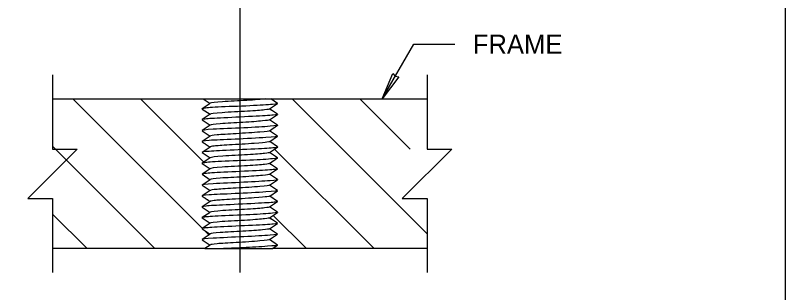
# Model space of a CAD drawing. Extents: x 99862 to 103151, y 100000 to 102076.
# Drawn here: x 102508 to 103151, y 100926 to 101158 of the extents above; entities that cross this region are included whole.
import ezdxf

# ---------------------------------------------------------------- set-up
doc = ezdxf.new("R2010")
doc.units = 0
for name, color, linetype in [('Level 1', 7, 'Continuous'), ('Level 14', 7, 'Continuous'), ('Level 15', 7, 'Continuous'), ('Level 17', 7, 'Continuous'), ('Level 2', 7, 'Continuous'), ('Level 20', 7, 'Continuous')]:
    doc.layers.add(name, color=color, linetype=linetype)

msp = doc.modelspace()

# ---------------------------------------------------------------- linework, layer by layer
at = {"layer": 'Level 1'}
for p, q in [((102665.01, 101087.88), (102670.7, 101084.06)), ((102727.12, 101084.12), (102721.51, 101087.88)), ((102670.7, 101084.06), (102664.02, 101079.63)), ((102664.18, 101079.39), (102670.73, 101075)), ((102720.39, 101079.5), (102727.12, 101083.97)), ((102727.06, 101075.02), (102720.39, 101079.5)), ((102670.73, 101075), (102664.05, 101070.59)), ((102720.45, 101070.41), (102727.12, 101074.81)), ((102664.05, 101070.37), (102670.75, 101065.88)), ((102670.75, 101065.88), (102664.05, 101061.42)), ((102720.4, 101061.28), (102727.12, 101065.79)), ((102727.12, 101065.93), (102720.45, 101070.41)), ((102664.05, 101061.21), (102670.73, 101056.73)), ((102727.12, 101056.77), (102720.4, 101061.28)), ((102670.73, 101056.73), (102664.11, 101052.33)), ((102720.5, 101052.19), (102727.12, 101056.62)), ((102670.76, 101047.7), (102664.11, 101043.24)), ((102720.45, 101043.13), (102727.12, 101047.61)), ((102727.12, 101047.75), (102720.5, 101052.19)), ((102664.11, 101043.02), (102670.7, 101038.61)), ((102727.12, 101038.66), (102720.45, 101043.13)), ((102670.7, 101038.61), (102664.02, 101034.17)), ((102664.18, 101033.93), (102670.73, 101029.54)), ((102720.39, 101034.04), (102727.12, 101038.52)), ((102727.06, 101029.57), (102720.39, 101034.04)), ((102670.73, 101029.54), (102664.05, 101025.13)), ((102720.45, 101024.95), (102727.12, 101029.35)), ((102664.05, 101024.92), (102670.75, 101020.42)), ((102670.75, 101020.42), (102664.05, 101015.97)), ((102720.4, 101015.82), (102727.12, 101020.33)), ((102727.12, 101020.48), (102720.45, 101024.95)), ((102664.05, 101015.75), (102670.73, 101011.27)), ((102727.12, 101011.32), (102720.4, 101015.82)), ((102670.73, 101011.27), (102664.11, 101006.88)), ((102720.5, 101006.73), (102727.12, 101011.17)), ((102670.76, 101002.24), (102664.11, 100997.79)), ((102720.45, 100997.68), (102727.12, 101002.15)), ((102727.12, 101002.3), (102720.5, 101006.73)), ((102664.11, 100997.57), (102670.7, 100993.16)), ((102727.12, 100993.21), (102720.45, 100997.68)), ((102670.7, 100993.16), (102664.02, 100988.72)), ((102664.18, 100988.48), (102670.73, 100984.09)), ((102720.39, 100988.59), (102727.12, 100993.06)), ((102727.06, 100984.12), (102720.39, 100988.59)), ((102670.73, 100984.09), (102664.05, 100979.68)), ((102720.45, 100979.5), (102727.12, 100983.9)), ((102664.05, 100979.46), (102670.75, 100974.97)), ((102727.12, 100975.02), (102720.45, 100979.5)), ((102670.75, 100974.97), (102664.05, 100970.52)), ((102664.05, 100970.3), (102670.73, 100965.82)), ((102720.4, 100970.37), (102727.12, 100974.88)), ((102727.12, 100965.86), (102720.4, 100970.37)), ((102670.73, 100965.82), (102666.3, 100962.88)), ((102722.89, 100962.88), (102727.12, 100965.72))]:
    msp.add_line(p, q, dxfattribs=at)
msp.add_lwpolyline([(99862, 99999.5), (103151, 99999.5), (103151, 102075.5), (99862, 102075.5)], close=True, dxfattribs=at)
for points in [[(102664.11, 101052.12), (102665.82, 101050.95), (102666.46, 101050.59)], [(102666.71, 101050.37), (102670.76, 101047.7)], [(102664.11, 101006.66), (102665.82, 101005.5), (102666.46, 101005.13)], [(102666.71, 101004.92), (102670.76, 101002.24)]]:
    msp.add_lwpolyline(points, dxfattribs=at)
at = {"layer": 'Level 14'}
for p, q in [((102665.01, 101087.88), (102721.51, 101087.88)), ((102666.3, 100962.88), (102722.89, 100962.88))]:
    msp.add_line(p, q, dxfattribs=at)
for points in [[(102720.48, 101079.44), (102722, 101078.44)], [(102720.48, 101033.99), (102722, 101032.99)], [(102720.48, 100988.53), (102722, 100987.53)]]:
    msp.add_lwpolyline(points, dxfattribs=at)
for points in [[(102717.1, 101087.88), (102713.94, 101087.48), (102702.24, 101086.52), (102679.3, 101085.57), (102671.52, 101084.55), (102670.88, 101084.19)], [(102727.12, 101084.12), (102727.37, 101083.97), (102725.47, 101083.39), (102705.99, 101082.01), (102673.67, 101080.99), (102663.55, 101079.9), (102663.93, 101079.39), (102663.99, 101079.39)], [(102720.22, 101079.39), (102720.1, 101079.32), (102718.01, 101078.73), (102703.78, 101077.5), (102678.47, 101076.41), (102670.76, 101075.39), (102670.76, 101074.95)], [(102727.12, 101075.02), (102727.37, 101074.88), (102726.04, 101074.3), (102708.65, 101073.28), (102675.88, 101071.75), (102663.86, 101070.95), (102663.93, 101070.44), (102664.05, 101070.37)], [(102727.12, 101065.93), (102727.5, 101065.72), (102723.89, 101065.06), (102699.79, 101063.61), (102670.12, 101062.52), (102663.42, 101061.64), (102664.05, 101061.21)], [(102720.22, 101070.3), (102719.91, 101070.08), (102716.56, 101069.5), (102698.91, 101068.19), (102677.02, 101067.17), (102671.45, 101066.37), (102670.95, 101066.01)], [(102720.35, 101061.28), (102720.41, 101060.92), (102714.72, 101060.26), (102691.57, 101058.66), (102674.49, 101057.86), (102671.33, 101057.13), (102671.01, 101056.92)], [(102727.12, 101056.77), (102727.69, 101056.41), (102720.67, 101055.75), (102690.43, 101054.08), (102666.9, 101053.21), (102663.67, 101052.41), (102664.11, 101052.12)], [(102727.12, 101047.75), (102727.25, 101047.68), (102727.12, 101047.17), (102714.4, 101046.22), (102681.45, 101044.77), (102664.81, 101043.82), (102663.86, 101043.17), (102664.11, 101043.02)], [(102720.29, 101052.12), (102720.29, 101052.12), (102719.59, 101051.68), (102710.36, 101050.73), (102684.55, 101049.28), (102672.53, 101048.48), (102671.07, 101047.9), (102670.95, 101047.82)], [(102720.22, 101043.02), (102720.1, 101042.95), (102718.01, 101042.37), (102703.78, 101041.13), (102679.3, 101040.12), (102671.52, 101039.1), (102670.88, 101038.73)], [(102727.12, 101038.66), (102727.37, 101038.52), (102725.47, 101037.93), (102705.99, 101036.55), (102673.67, 101035.53), (102663.55, 101034.44), (102663.93, 101033.93), (102663.99, 101033.93)], [(102720.22, 101033.93), (102720.1, 101033.86), (102718.01, 101033.28), (102703.78, 101032.04), (102678.47, 101030.95), (102670.76, 101029.93), (102670.76, 101029.5)], [(102727.12, 101029.57), (102727.37, 101029.42), (102726.04, 101028.84), (102708.65, 101027.82), (102675.88, 101026.3), (102663.86, 101025.5), (102663.93, 101024.99), (102664.05, 101024.92)], [(102727.12, 101020.48), (102727.5, 101020.26), (102723.89, 101019.61), (102699.79, 101018.15), (102670.12, 101017.06), (102663.42, 101016.19), (102664.05, 101015.75)], [(102720.22, 101024.84), (102719.91, 101024.62), (102716.56, 101024.04), (102698.91, 101022.73), (102677.02, 101021.72), (102671.45, 101020.92), (102670.95, 101020.55)], [(102720.35, 101015.82), (102720.41, 101015.46), (102714.72, 101014.81), (102691.57, 101013.21), (102674.49, 101012.41), (102671.33, 101011.68), (102671.01, 101011.46)], [(102727.12, 101011.32), (102727.69, 101010.95), (102720.67, 101010.3), (102690.43, 101008.62), (102666.9, 101007.75), (102663.67, 101006.95), (102664.11, 101006.66)], [(102727.12, 101002.3), (102727.25, 101002.22), (102727.12, 101001.72), (102714.4, 101000.77), (102681.45, 100999.32), (102664.81, 100998.37), (102663.86, 100997.72), (102664.11, 100997.57)], [(102720.29, 101006.66), (102720.29, 101006.66), (102719.59, 101006.22), (102710.36, 101005.28), (102684.55, 101003.82), (102672.53, 101003.02), (102671.07, 101002.44), (102670.95, 101002.37)], [(102720.22, 100997.57), (102720.1, 100997.5), (102718.01, 100996.92), (102703.78, 100995.68), (102679.3, 100994.66), (102671.52, 100993.64), (102670.88, 100993.28)], [(102727.12, 100993.21), (102727.37, 100993.06), (102725.47, 100992.48), (102705.99, 100991.1), (102673.67, 100990.08), (102663.55, 100988.99), (102663.93, 100988.48), (102663.99, 100988.48)], [(102720.22, 100988.48), (102720.1, 100988.41), (102718.01, 100987.82), (102703.78, 100986.59), (102678.47, 100985.5), (102670.76, 100984.48), (102670.76, 100984.04)], [(102727.12, 100984.12), (102727.37, 100983.97), (102726.04, 100983.39), (102708.65, 100982.37), (102675.88, 100980.84), (102663.86, 100980.04), (102663.93, 100979.53), (102664.05, 100979.46)], [(102720.22, 100979.39), (102719.91, 100979.17), (102716.56, 100978.59), (102698.91, 100977.28), (102677.02, 100976.26), (102671.45, 100975.46), (102670.95, 100975.1)], [(102727.12, 100975.02), (102727.5, 100974.81), (102723.89, 100974.15), (102699.79, 100972.7), (102670.12, 100971.61), (102663.42, 100970.73), (102664.05, 100970.3)], [(102720.35, 100970.37), (102720.41, 100970.01), (102714.72, 100969.35), (102691.57, 100967.75), (102674.49, 100966.95), (102671.33, 100966.22), (102671.01, 100966.01)], [(102727.12, 100965.86), (102727.69, 100965.5), (102720.67, 100964.84), (102697.45, 100963.56), (102684.93, 100963.01), (102682.06, 100962.88)]]:
    msp.add_open_spline(points, degree=3, dxfattribs=at)
at = {"layer": 'Level 15'}
for p, q in [((102695.55, 101597.87), (102695.55, 100942.88)), ((102814.32, 101087.88), (102840.64, 101133.47)), ((102840.64, 101133.47), (102874.95, 101133.47))]:
    msp.add_line(p, q, dxfattribs=at)
for points in [[(102539.29, 101107.88), (102539.29, 101046.03), (102559.94, 101046.03), (102518.64, 101004.73), (102539.29, 101004.73), (102539.29, 100942.88)], [(102851.82, 101107.88), (102851.82, 101046.03), (102872.47, 101046.03), (102831.17, 101004.73), (102851.82, 101004.73), (102851.82, 100942.88)]]:
    msp.add_lwpolyline(points, dxfattribs=at)
msp.add_lwpolyline([(102814.32, 101087.88), (102823.15, 101109.14), (102825.21, 101106.73), (102828.32, 101106.16)], close=True, dxfattribs=at)
at = {"layer": 'Level 17'}
for p, q in [((102556.24, 101087.88), (102664.33, 100979.79)), ((102612.81, 101087.88), (102665.62, 101035.07)), ((102739.27, 101087.88), (102851.82, 100975.33)), ((102795.84, 101087.88), (102837.69, 101046.03)), ((102539.29, 101048.26), (102624.67, 100962.88)), ((102724.64, 101045.94), (102807.7, 100962.88)), ((102668.57, 101003.83), (102670.41, 101001.99)), ((102539.29, 100991.7), (102568.1, 100962.88)), ((102723.45, 100990.56), (102751.13, 100962.88)), ((102665.7, 100978.41), (102669.81, 100974.31)), ((102539.29, 100963.41), (102539.82, 100962.88))]:
    msp.add_line(p, q, dxfattribs=at)
at = {"layer": 'Level 2'}
for p, q in [((102539.29, 101087.88), (102665.01, 101087.88)), ((102721.51, 101087.88), (102851.82, 101087.88)), ((102666.3, 100962.88), (102539.29, 100962.88)), ((102851.82, 100962.88), (102722.89, 100962.88))]:
    msp.add_line(p, q, dxfattribs=at)

# ---------------------------------------------------------------- texts
at = {"layer": 'Level 20'}
msp.add_text('FRAME', height=16, rotation=360, dxfattribs=at).set_placement((102889.94, 101125.47))

doc.saveas('drawing.dxf')
